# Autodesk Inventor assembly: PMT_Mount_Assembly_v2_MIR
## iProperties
Shininess: 64.0
Length Units: 11272
Angle Units: 11279
Time Units: 11290
Mass Units: 11286
Length Display Precision: 3
Angle Display Precision: 2
Compacted: True
Part Number: PMT_Mount_Assembly_v2_MIR
Document SubType Name: Assembly
Created: 2004-08
Designer: John Blackburn
Manufacturer: Standard
Standards Organization: Custom
Density: 0.0
Volumn: 0.0
Area: 0.0
PropertySet Name: Model Information
Control State: 0
Master: False
Checked Out: False
Author: John Blackburn
